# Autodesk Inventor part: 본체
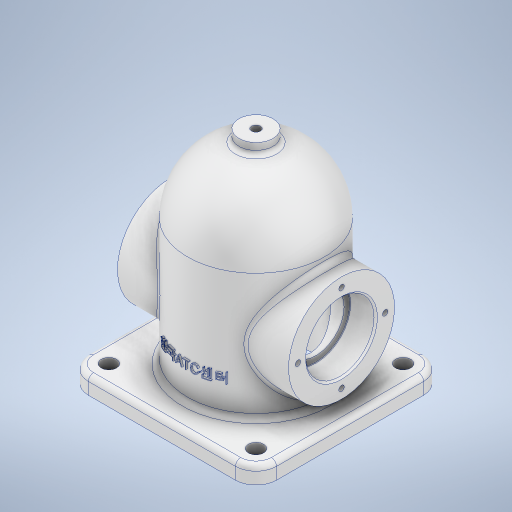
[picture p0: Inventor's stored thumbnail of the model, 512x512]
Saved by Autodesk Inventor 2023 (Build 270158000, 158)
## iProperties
Created: 2025-04
Part Number: 본체
Material: 알루미늄 6061
Document SubType Name: Modeling
Designer: Admin
Density: 2.7 g/cm^3
Appearance: 알루미늄 - 평지
Mass: 865.972 g
Surface Area: 801.981 cm^2
Volume: 320.731 cm^3
Author: Admin
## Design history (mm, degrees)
sketch "스케치1"
  geometry: L1 (-57.941, 0)-(9.657, 0) reference; L2 (-40, 0)-(0, 0); L3 (0, -84)-(-40, -84); L4 (-40, -84)-(-40, 0); L5 (0, -110.457)-(0, 74.741) reference; L6 (0, 40)-(0, -84); A1 r 40 centre (0, 0) between (0, 40) and (-40, 0); 1 further point
  constraints: 8 end point, 4 point on line, 2 point on circle, 1 centre point, 1 coincident, 1 collinear, 1 horizontal, 1 parallel, 1 perpendicular
  dimensions: "d1" = 40 radius of A1; "d2" = 84 distance between parallel lines of L1 L3
revolve "회전1" sketch "스케치1" stored, may be unused: angle "d3" = 90 deg
sketch "스케치3"
  geometry: L1 (-55, -55)-(55, -55); L2 (55, -55)-(55, 55); L3 (55, 55)-(-55, 55); L4 (-55, 55)-(-55, -55); L5 (-55, -55)-(55, 55); L6 (55, -55)-(-55, 55); 1 further point
  constraints: 12 end point, 2 midpoint, 2 parallel, 1 horizontal, 1 perpendicular
  dimensions: "d10" = 110 distance of L2.end L3.end; "d11" = 110 distance of L1.end L2.end
extrude "돌출1" join sketch "스케치3" distance "d12" = 10; taper "d13" = 0 deg
sketch "스케치4"
  geometry: C1 r 10 at (55, -55); 1 further point
  constraints: 1 centre point, 1 coincident
  dimensions: "d14" = 20 diameter of C1
extrude "돌출2" join sketch "스케치4" distance "d15" = 129; taper "d16" = 0 deg
sketch "스케치5"
  geometry: L1 (0, -77)-(0, 77) reference; L2 (-100.8, 0)-(16.8, 0) reference; L3 (-84, 55)-(-84, -55) reference; C1 r 31 at (-36, 0); 1 further point
  constraints: 1 centre point, 1 point on line
  dimensions: "d17" = 62 diameter of C1; "d21" = 48 distance from line of L3 C1.centre
extrude "돌출3" join sketch "스케치5" stored distance "d19" = 100; taper "d20" = 0 deg
sketch "스케치6"
  geometry: L1 (-77, 0)-(77, 0) reference; L2 (40, 0)-(-40, 0) reference; L3 (-32, -84)-(-32, 0); L4 (-32, -84)-(0, -84); L5 (-55, -84)-(55, -84) reference; L6 (0, -108.525)-(0, 63.153) reference; L7 (0, 32)-(0, -84); A1 r 32 centre (0, 0) between (0, 32) and (-32, 0); 1 further point
  constraints: 6 end point, 2 point on circle, 1 centre point, 1 coincident, 1 collinear, 1 midpoint, 1 point on line
  dimensions: "d22" = 32 radius of A1; "d23" = 84 distance of L3.start L3.end; "d25" = 32 distance of L3.start L4.end
revolve "회전3" sketch "스케치6" stored, may be unused: angle "d26" = 90 deg
sketch "스케치7"
  geometry: L1 (0, -73.8)-(0, 106.8) reference; L2 (77, 36)-(-77, 36) reference; C1 r 20 at (0, 0); C2 r 31 at (0, 0) reference; 1 further point
  constraints: 1 centre point, 1 concentric, 1 point on line
  dimensions: "d27" = 40 diameter of C1
extrude "돌출4" cut sketch "스케치7" distance "d28" = 15; taper "d29" = 0 deg
sketch "스케치8"
  geometry: C1 r 16.5 at (0, 0); C2 r 31 at (0, 0) reference; 1 further point
  constraints: 1 centre point, 1 concentric
  dimensions: "d30" = 33 diameter of C1
extrude "돌출5" cut sketch "스케치8" stored distance "d31" = 15; taper "d32" = 0 deg
sketch "스케치9" dims "d33" = 51
  geometry: L1 (0, -73.8)-(0, 106.8) reference; L2 (-77, 36)-(77, 36) reference; C1 r 31 at (0, 0) reference; 3 further points
  constraints: 1 point on line, 1 vertical alignment, 3 other
hole "구멍1" sketch "스케치9" at (0, 25.5) diameter "d34" = 3.242; stored, may be unused: countersink angle "d38" = 90 deg, drill point angle "d40" = 118 deg; dims "d35" = 8, "d36" = 4, "d37" = 2, "d39" = 10
sketch "스케치10"
  geometry: 2 further points
  constraints: 1 coincident
hole "구멍2" sketch "스케치10" at (0, 0) diameter "d44" = 5.1881; stored, may be unused: countersink angle "d48" = 90 deg, drill point angle "d50" = 0 deg; dims "d45" = 15, "d46" = 4, "d47" = 2, "d49" = 12
fillet "모깎기1" dims "d51" = 12
sketch "스케치11"
  geometry: C1 r 4.5 at (-43, 43); A1 r 12 centre (-43, 43) between (-43, 55) and (-55, 43) reference; 1 further point
  constraints: 1 centre point, 1 concentric
  dimensions: "d53" = 9 diameter of C1
extrude "돌출6" cut sketch "스케치11" stored distance "d54" = 10; taper "d55" = 0 deg
fillet "모깎기2" dims "d56" = 3
fillet "모깎기3" dims "d57" = 3
fillet "모깎기4" dims "d58" = 3
fillet "모깎기5" dims "d59" = 3
fillet "모깎기6" dims "d60" = 0.3
chamfer "모따기1" distance "d61" = 1; stored, may be unused: second distance "d62" = 2, angle "d63" = 45 deg
node "작업 평면1"
sketch "스케치12"
  geometry: L1 (0, -100.8)-(0, 16.8) reference; L2 (-60.2, 0)-(60.2, 0) reference; L3 (43, -84)-(-43, -84) reference; 2 further points
  constraints: 1 point on line, 1 other
  dimensions: "d65" = 30 distance from line of L3 point (0, -54)
feature "엠보싱1" sketch "스케치12" dims "d14" = 20, "d66" = 1, "d67" = 0
node "솔리드1"
mirror "미러1"
pattern_circular "원형 패턴1" dims angle "d42" = 360 deg
mirror "미러2"
mirror "미러3"
mirror "미러4"
feature "A9D066F2-1C7D-4E18-AEED-F7BC21143FA4" dims "d34" = 3.242, "d35" = 8, "d36" = 4, "d37" = 2, "d38" = 90 deg, "d39" = 10, "d40" = 118 deg
other parameters: "d64" = 110.25
